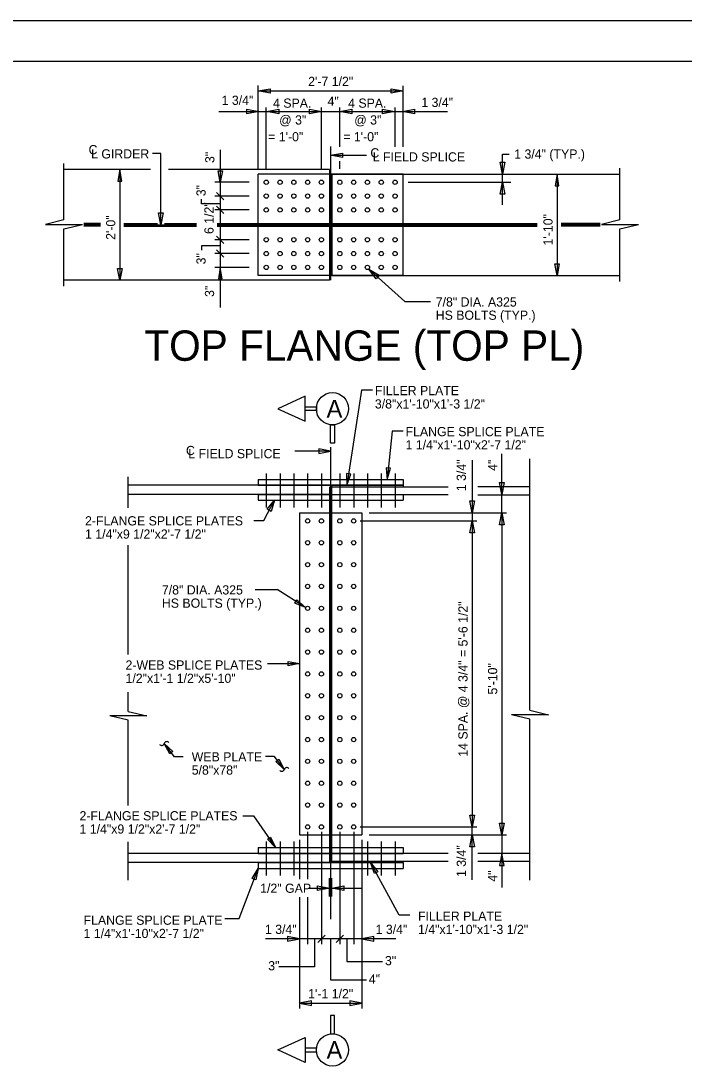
# Model space of a CAD drawing. Extents: x 1970675.2 to 1970715, y 796143 to 796167.2.
# Drawn here: x 1970692.92 to 1970701.93, y 796153.05 to 796167.25 of the extents above; entities that cross this region are included whole.
import ezdxf

# ---------------------------------------------------------------- set-up
doc = ezdxf.new("R2010")
doc.units = 0
for name, color, linetype in [('BR_AUTO DIMENSION', 7, 'Continuous'), ('BR_BORDER LINES', 7, 'Continuous'), ('BR_CENTER LINES', 7, 'Continuous'), ('BR_STRUCTURAL STEEL', 7, 'Continuous'), ('BR_TEXT', 7, 'Continuous'), ('Default', 7, 'Continuous'), ('Level 31', 7, 'Continuous')]:
    doc.layers.add(name, color=color, linetype=linetype)

msp = doc.modelspace()

# ---------------------------------------------------------------- linework, layer by layer
at = {"layer": 'BR_AUTO DIMENSION'}
for p, q in [((1970696.144, 796165.236), (1970696.144, 796166.368)), ((1970696.144, 796166.295), (1970698.113, 796166.295)), ((1970698.113, 796165.537), (1970698.113, 796166.366)), ((1970695.609, 796166.015), (1970698.716, 796166.015)), ((1970696.253, 796165.236), (1970696.253, 796166.071)), ((1970697.003, 796165.236), (1970697.003, 796166.071)), ((1970697.253, 796165.538), (1970697.253, 796166.071)), ((1970698.003, 796165.538), (1970698.003, 796166.071)), ((1970694.822, 796165.447), (1970694.706, 796165.447)), ((1970694.822, 796164.477), (1970694.822, 796165.447)), ((1970695.629, 796165.497), (1970695.629, 796163.356)), ((1970699.464, 796164.749), (1970699.464, 796165.436)), ((1970699.464, 796165.436), (1970699.551, 796165.436)), ((1970697.253, 796165.236), (1970697.253, 796165.343)), ((1970694.264, 796165.227), (1970694.264, 796163.727)), ((1970698.18, 796165.164), (1970699.574, 796165.164)), ((1970700.204, 796165.164), (1970700.204, 796163.789)), ((1970696.022, 796165.055), (1970695.553, 796165.055)), ((1970698.18, 796165.055), (1970699.574, 796165.055)), ((1970696.022, 796164.868), (1970695.553, 796164.868)), ((1970695.679, 796164.817), (1970695.579, 796164.918)), ((1970695.679, 796164.629), (1970695.579, 796164.731)), ((1970696.022, 796164.68), (1970695.553, 796164.68)), ((1970695.679, 796164.223), (1970695.579, 796164.324)), ((1970696.022, 796164.274), (1970695.553, 796164.274)), ((1970696.022, 796164.086), (1970695.553, 796164.086)), ((1970695.679, 796164.036), (1970695.579, 796164.137)), ((1970696.022, 796163.899), (1970695.553, 796163.899)), ((1970698.138, 796163.436), (1970697.647, 796163.876)), ((1970698.138, 796163.436), (1970698.486, 796163.436)), ((1970697.549, 796162.229), (1970697.349, 796160.94)), ((1970697.695, 796162.229), (1970697.549, 796162.229)), ((1970697.966, 796161.673), (1970697.896, 796161.018)), ((1970698.112, 796161.673), (1970697.966, 796161.673)), ((1970699.453, 796160.565), (1970699.453, 796161.365)), ((1970699.05, 796161.279), (1970699.05, 796160.455)), ((1970696.219, 796160.461), (1970696.365, 796160.736)), ((1970696.083, 796160.461), (1970696.219, 796160.461)), ((1970697.652, 796160.565), (1970699.516, 796160.565)), ((1970699.453, 796160.565), (1970699.453, 796156.19)), ((1970697.527, 796160.455), (1970699.113, 796160.455)), ((1970699.05, 796160.455), (1970699.05, 796156.299)), ((1970696.104, 796159.522), (1970696.4, 796159.522)), ((1970696.788, 796159.278), (1970696.4, 796159.522)), ((1970696.269, 796158.517), (1970696.707, 796158.517)), ((1970695.009, 796157.251), (1970694.868, 796157.432)), ((1970695.123, 796157.251), (1970695.009, 796157.251)), ((1970696.243, 796157.261), (1970696.358, 796157.261)), ((1970696.358, 796157.261), (1970696.499, 796157.08)), ((1970695.934, 796156.451), (1970696.08, 796156.451)), ((1970696.08, 796156.451), (1970696.381, 796156.018)), ((1970696.816, 796156.231), (1970696.816, 796155.589)), ((1970697.003, 796156.231), (1970697.003, 796154.706)), ((1970697.253, 796156.231), (1970697.253, 796154.706)), ((1970697.441, 796156.231), (1970697.441, 796154.706)), ((1970697.527, 796156.299), (1970699.113, 796156.299)), ((1970699.05, 796155.58), (1970699.05, 796156.299)), ((1970696.707, 796156.122), (1970696.707, 796155.589)), ((1970697.55, 796156.122), (1970697.55, 796153.832)), ((1970697.652, 796156.19), (1970699.516, 796156.19)), ((1970699.453, 796156.19), (1970699.453, 796155.477)), ((1970698.059, 796155.102), (1970697.671, 796155.815)), ((1970695.886, 796155.056), (1970696.144, 796155.736)), ((1970697.113, 796155.355), (1970697.113, 796155.601)), ((1970697.144, 796155.355), (1970697.144, 796155.601)), ((1970696.826, 796155.467), (1970697.113, 796155.467)), ((1970697.144, 796155.467), (1970697.56, 796155.467)), ((1970696.707, 796155.347), (1970696.707, 796153.832)), ((1970696.816, 796155.347), (1970696.816, 796154.706)), ((1970698.205, 796155.102), (1970698.059, 796155.102)), ((1970695.693, 796155.056), (1970695.886, 796155.056)), ((1970697.054, 796154.829), (1970696.953, 796154.729)), ((1970697.304, 796154.829), (1970697.203, 796154.729)), ((1970698.014, 796154.779), (1970696.243, 796154.779)), ((1970696.91, 796154.779), (1970696.91, 796154.401)), ((1970697.128, 796154.779), (1970697.128, 796154.221)), ((1970697.347, 796154.779), (1970697.347, 796154.471)), ((1970696.91, 796154.401), (1970696.423, 796154.401)), ((1970697.347, 796154.471), (1970697.834, 796154.471)), ((1970697.128, 796154.221), (1970697.615, 796154.221)), ((1970696.707, 796153.905), (1970697.55, 796153.905))]:
    msp.add_line(p, q, dxfattribs=at)
for points in [[(1970696.307, 796166.264), (1970696.144, 796166.295), (1970696.307, 796166.326)], [(1970697.95, 796166.326), (1970698.113, 796166.295), (1970697.95, 796166.264)], [(1970695.989, 796166.046), (1970696.152, 796166.015), (1970695.989, 796165.984)], [(1970696.424, 796165.984), (1970696.261, 796166.015), (1970696.424, 796166.046)], [(1970696.841, 796166.046), (1970697.003, 796166.015), (1970696.841, 796165.984)], [(1970697.416, 796165.984), (1970697.253, 796166.015), (1970697.416, 796166.046)], [(1970697.833, 796166.046), (1970697.996, 796166.015), (1970697.833, 796165.984)], [(1970698.268, 796165.984), (1970698.105, 796166.015), (1970698.268, 796166.046)], [(1970697.291, 796165.389), (1970697.128, 796165.421), (1970697.291, 796165.452)], [(1970699.495, 796165.327), (1970699.464, 796165.164), (1970699.432, 796165.327)], [(1970694.238, 796165.071), (1970694.29, 796165.071), (1970694.264, 796165.227)], [(1970695.659, 796165.211), (1970695.629, 796165.055), (1970695.599, 796165.211)], [(1970700.178, 796165.008), (1970700.23, 796165.008), (1970700.204, 796165.164)], [(1970699.432, 796164.893), (1970699.464, 796165.055), (1970699.495, 796164.893)], [(1970694.853, 796164.639), (1970694.822, 796164.477), (1970694.79, 796164.639)], [(1970694.294, 796163.883), (1970694.264, 796163.727), (1970694.234, 796163.883)], [(1970695.603, 796163.742), (1970695.655, 796163.742), (1970695.629, 796163.899)], [(1970697.747, 796163.744), (1970697.647, 796163.876), (1970697.788, 796163.791)], [(1970700.234, 796163.945), (1970700.204, 796163.789), (1970700.174, 796163.945)], [(1970696.966, 796161.371), (1970697.128, 796161.403), (1970696.966, 796161.434)], [(1970697.883, 796161.176), (1970697.896, 796161.018), (1970697.942, 796161.17)], [(1970697.343, 796161.098), (1970697.349, 796160.94), (1970697.402, 796161.089)], [(1970699.484, 796160.977), (1970699.453, 796160.815), (1970699.422, 796160.977)], [(1970696.265, 796160.613), (1970696.365, 796160.736), (1970696.318, 796160.585)], [(1970699.082, 796160.727), (1970699.05, 796160.565), (1970699.019, 796160.727)], [(1970699.422, 796160.402), (1970699.453, 796160.565), (1970699.484, 796160.402)], [(1970699.019, 796160.293), (1970699.05, 796160.455), (1970699.082, 796160.293)], [(1970696.642, 796159.339), (1970696.67, 796159.383), (1970696.788, 796159.278)], [(1970696.551, 796158.547), (1970696.707, 796158.517), (1970696.551, 796158.487)], [(1970694.984, 796157.324), (1970694.943, 796157.292), (1970694.868, 796157.432)], [(1970696.382, 796157.187), (1970696.424, 796157.219), (1970696.499, 796157.08)], [(1970699.082, 796156.461), (1970699.05, 796156.299), (1970699.019, 796156.461)], [(1970699.484, 796156.352), (1970699.453, 796156.19), (1970699.422, 796156.352)], [(1970696.27, 796156.131), (1970696.313, 796156.161), (1970696.381, 796156.018)], [(1970699.019, 796156.027), (1970699.05, 796156.19), (1970699.082, 796156.027)], [(1970699.484, 796155.777), (1970699.453, 796155.94), (1970699.422, 796155.777)], [(1970697.768, 796155.69), (1970697.723, 796155.665), (1970697.671, 796155.815)], [(1970696.112, 796155.581), (1970696.063, 796155.6), (1970696.144, 796155.736)], [(1970696.95, 796155.498), (1970697.113, 796155.467), (1970696.95, 796155.436)], [(1970697.307, 796155.436), (1970697.144, 796155.467), (1970697.307, 796155.498)], [(1970696.544, 796154.748), (1970696.707, 796154.779), (1970696.544, 796154.81)], [(1970697.713, 796154.81), (1970697.55, 796154.779), (1970697.713, 796154.748)], [(1970696.869, 796153.936), (1970696.707, 796153.905), (1970696.869, 796153.874)], [(1970697.388, 796153.874), (1970697.55, 796153.905), (1970697.388, 796153.936)]]:
    msp.add_lwpolyline(points, close=True, dxfattribs=at)
for points in [[(1970697.128, 796165.421), (1970697.614, 796165.421)], [(1970695.629, 796164.762), (1970695.376, 796164.762), (1970695.376, 796164.823)], [(1970695.629, 796164.192), (1970695.376, 796164.192), (1970695.376, 796164.131)], [(1970697.128, 796161.403), (1970696.643, 796161.403)]]:
    msp.add_lwpolyline(points, dxfattribs=at)
at = {"layer": 'BR_BORDER LINES'}
msp.add_line((1970714.286, 796166.696), (1970677.253, 796166.696), dxfattribs=at)
at = {"layer": 'BR_CENTER LINES'}
for p, q in [((1970697.128, 796165.541), (1970697.128, 796163.727)), ((1970694.001, 796164.477), (1970693.777, 796164.477)), ((1970694.317, 796164.477), (1970694.822, 796164.477)), ((1970694.822, 796164.477), (1970695.307, 796164.477)), ((1970695.587, 796164.477), (1970699.932, 796164.477)), ((1970700.79, 796164.477), (1970700.258, 796164.477)), ((1970697.128, 796161.459), (1970697.128, 796155.048))]:
    msp.add_line(p, q, dxfattribs=at)
at = {"layer": 'BR_STRUCTURAL STEEL'}
for p, q in [((1970694.682, 796165.227), (1970693.506, 796165.227)), ((1970697.113, 796165.227), (1970694.924, 796165.227)), ((1970698.113, 796165.164), (1970696.144, 796165.164)), ((1970696.144, 796163.789), (1970696.144, 796165.164)), ((1970697.113, 796165.227), (1970697.113, 796165.164)), ((1970697.113, 796165.164), (1970697.113, 796163.789)), ((1970697.144, 796165.164), (1970697.144, 796163.789)), ((1970697.144, 796165.164), (1970701.058, 796165.164)), ((1970698.113, 796163.789), (1970698.113, 796165.164)), ((1970694.001, 796164.496), (1970693.777, 796164.496)), ((1970694.001, 796164.457), (1970693.777, 796164.457)), ((1970694.317, 796164.496), (1970694.777, 796164.496)), ((1970694.317, 796164.457), (1970695.308, 796164.457)), ((1970694.872, 796164.496), (1970695.308, 796164.496)), ((1970695.588, 796164.496), (1970697.113, 796164.496)), ((1970695.588, 796164.457), (1970697.113, 796164.457)), ((1970697.144, 796164.496), (1970699.932, 796164.496)), ((1970697.144, 796164.457), (1970699.933, 796164.457)), ((1970700.79, 796164.496), (1970700.258, 796164.496)), ((1970700.79, 796164.457), (1970700.258, 796164.457)), ((1970697.113, 796163.727), (1970693.506, 796163.727)), ((1970698.113, 796163.789), (1970696.144, 796163.789)), ((1970697.113, 796163.789), (1970697.113, 796163.727)), ((1970697.144, 796163.789), (1970701.058, 796163.789)), ((1970696.253, 796161.099), (1970696.253, 796160.639)), ((1970696.441, 796161.099), (1970696.441, 796160.639)), ((1970696.628, 796161.099), (1970696.628, 796160.639)), ((1970696.816, 796161.099), (1970696.816, 796160.639)), ((1970697.003, 796161.099), (1970697.003, 796160.639)), ((1970697.253, 796161.099), (1970697.253, 796160.639)), ((1970697.441, 796161.099), (1970697.441, 796160.639)), ((1970697.628, 796161.099), (1970697.628, 796160.639)), ((1970697.816, 796161.099), (1970697.816, 796160.639)), ((1970698.003, 796161.099), (1970698.003, 796160.639)), ((1970697.113, 796160.94), (1970694.378, 796160.94)), ((1970696.144, 796161.018), (1970696.144, 796160.94)), ((1970696.144, 796161.018), (1970698.113, 796161.018)), ((1970696.144, 796160.94), (1970698.113, 796160.94)), ((1970697.113, 796160.916), (1970697.113, 796155.815)), ((1970697.144, 796155.815), (1970697.144, 796160.94)), ((1970698.113, 796160.94), (1970697.144, 796160.94)), ((1970697.144, 796160.916), (1970697.144, 796160.94)), ((1970697.144, 796160.916), (1970698.725, 796160.916)), ((1970697.144, 796160.916), (1970698.113, 796160.916)), ((1970698.113, 796161.018), (1970698.113, 796160.94)), ((1970698.113, 796160.94), (1970698.113, 796160.916)), ((1970699.836, 796160.916), (1970699.128, 796160.916)), ((1970697.113, 796160.815), (1970694.378, 796160.815)), ((1970696.144, 796160.815), (1970696.144, 796160.736)), ((1970696.144, 796160.815), (1970698.113, 796160.815)), ((1970697.144, 796160.815), (1970698.725, 796160.815)), ((1970698.113, 796160.815), (1970698.113, 796160.736)), ((1970699.836, 796160.807), (1970699.128, 796160.807)), ((1970696.144, 796160.736), (1970698.113, 796160.736)), ((1970696.707, 796160.565), (1970697.55, 796160.565)), ((1970696.707, 796160.565), (1970696.707, 796156.19)), ((1970697.55, 796160.565), (1970697.55, 796156.19)), ((1970696.253, 796156.099), (1970696.253, 796155.639)), ((1970696.441, 796156.099), (1970696.441, 796155.639)), ((1970696.628, 796156.099), (1970696.628, 796155.639)), ((1970696.707, 796156.19), (1970697.55, 796156.19)), ((1970696.816, 796156.099), (1970696.816, 796155.639)), ((1970697.003, 796156.099), (1970697.003, 796155.639)), ((1970697.253, 796156.099), (1970697.253, 796155.639)), ((1970697.441, 796156.099), (1970697.441, 796155.639)), ((1970697.628, 796156.099), (1970697.628, 796155.639)), ((1970697.816, 796156.099), (1970697.816, 796155.639)), ((1970698.003, 796156.099), (1970698.003, 796155.639)), ((1970698.725, 796155.94), (1970694.378, 796155.94)), ((1970696.144, 796156.018), (1970696.144, 796155.94)), ((1970696.144, 796156.018), (1970698.113, 796156.018)), ((1970696.144, 796155.94), (1970698.113, 796155.94)), ((1970698.113, 796156.018), (1970698.113, 796155.94)), ((1970699.836, 796155.94), (1970699.128, 796155.94)), ((1970697.113, 796155.815), (1970694.378, 796155.815)), ((1970696.144, 796155.815), (1970696.144, 796155.736)), ((1970696.144, 796155.815), (1970698.113, 796155.815)), ((1970697.144, 796155.83), (1970698.113, 796155.83)), ((1970697.144, 796155.815), (1970697.144, 796155.83)), ((1970698.725, 796155.83), (1970697.144, 796155.83)), ((1970698.113, 796155.815), (1970697.144, 796155.815)), ((1970698.113, 796155.815), (1970698.113, 796155.83)), ((1970698.113, 796155.815), (1970698.113, 796155.736)), ((1970699.836, 796155.83), (1970699.128, 796155.83)), ((1970696.144, 796155.736), (1970698.113, 796155.736))]:
    msp.add_line(p, q, dxfattribs=at)
for centre in [(1970696.253, 796165.055), (1970696.253, 796165.055), (1970696.441, 796165.055), (1970696.441, 796165.055), (1970696.628, 796165.055), (1970696.628, 796165.055), (1970696.816, 796165.055), (1970696.816, 796165.055), (1970697.003, 796165.055), (1970697.003, 796165.055), (1970697.253, 796165.055), (1970697.253, 796165.055), (1970697.441, 796165.055), (1970697.441, 796165.055), (1970697.628, 796165.055), (1970697.628, 796165.055), (1970697.816, 796165.055), (1970697.816, 796165.055), (1970698.003, 796165.055), (1970698.003, 796165.055), (1970696.253, 796164.868), (1970696.253, 796164.868), (1970696.441, 796164.868), (1970696.441, 796164.868), (1970696.628, 796164.868), (1970696.628, 796164.868), (1970696.816, 796164.868), (1970696.816, 796164.868), (1970697.003, 796164.868), (1970697.003, 796164.868), (1970697.253, 796164.868), (1970697.253, 796164.868), (1970697.441, 796164.868), (1970697.441, 796164.868), (1970697.628, 796164.868), (1970697.628, 796164.868), (1970697.816, 796164.868), (1970697.816, 796164.868), (1970698.003, 796164.868), (1970698.003, 796164.868), (1970696.253, 796164.68), (1970696.253, 796164.68), (1970696.441, 796164.68), (1970696.441, 796164.68), (1970696.628, 796164.68), (1970696.628, 796164.68), (1970696.816, 796164.68), (1970696.816, 796164.68), (1970697.003, 796164.68), (1970697.003, 796164.68), (1970697.253, 796164.68), (1970697.253, 796164.68), (1970697.441, 796164.68), (1970697.441, 796164.68), (1970697.628, 796164.68), (1970697.628, 796164.68), (1970697.816, 796164.68), (1970697.816, 796164.68), (1970698.003, 796164.68), (1970698.003, 796164.68), (1970696.253, 796164.274), (1970696.253, 796164.274), (1970696.441, 796164.274), (1970696.441, 796164.274), (1970696.628, 796164.274), (1970696.628, 796164.274), (1970696.816, 796164.274), (1970696.816, 796164.274), (1970697.003, 796164.274), (1970697.003, 796164.274), (1970697.253, 796164.274), (1970697.253, 796164.274), (1970697.441, 796164.274), (1970697.441, 796164.274), (1970697.628, 796164.274), (1970697.628, 796164.274), (1970697.816, 796164.274), (1970697.816, 796164.274), (1970698.003, 796164.274), (1970698.003, 796164.274), (1970696.253, 796164.086), (1970696.253, 796164.086), (1970696.441, 796164.086), (1970696.441, 796164.086), (1970696.628, 796164.086), (1970696.628, 796164.086), (1970696.816, 796164.086), (1970696.816, 796164.086), (1970697.003, 796164.086), (1970697.003, 796164.086), (1970697.253, 796164.086), (1970697.253, 796164.086), (1970697.441, 796164.086), (1970697.441, 796164.086), (1970697.628, 796164.086), (1970697.628, 796164.086), (1970697.816, 796164.086), (1970697.816, 796164.086), (1970698.003, 796164.086), (1970698.003, 796164.086), (1970696.253, 796163.899), (1970696.253, 796163.899), (1970696.441, 796163.899), (1970696.441, 796163.899), (1970696.628, 796163.899), (1970696.628, 796163.899), (1970696.816, 796163.899), (1970696.816, 796163.899), (1970697.003, 796163.899), (1970697.003, 796163.899), (1970697.253, 796163.899), (1970697.253, 796163.899), (1970697.441, 796163.899), (1970697.441, 796163.899), (1970697.628, 796163.899), (1970697.628, 796163.899), (1970697.816, 796163.899), (1970697.816, 796163.899), (1970698.003, 796163.899), (1970698.003, 796163.899), (1970696.816, 796160.455), (1970697.003, 796160.455), (1970697.253, 796160.455), (1970697.441, 796160.455), (1970696.816, 796160.158), (1970697.003, 796160.158), (1970697.253, 796160.158), (1970697.441, 796160.158), (1970696.816, 796159.861), (1970697.003, 796159.861), (1970697.253, 796159.861), (1970697.441, 796159.861), (1970696.816, 796159.565), (1970697.003, 796159.565), (1970697.253, 796159.565), (1970697.441, 796159.565), (1970696.816, 796159.268), (1970697.003, 796159.268), (1970697.253, 796159.268), (1970697.441, 796159.268), (1970696.816, 796158.971), (1970697.003, 796158.971), (1970697.253, 796158.971), (1970697.441, 796158.971), (1970696.816, 796158.674), (1970697.003, 796158.674), (1970697.253, 796158.674), (1970697.441, 796158.674), (1970696.816, 796158.377), (1970697.003, 796158.377), (1970697.253, 796158.377), (1970697.441, 796158.377), (1970696.816, 796158.08), (1970697.003, 796158.08), (1970697.253, 796158.08), (1970697.441, 796158.08), (1970696.816, 796157.783), (1970697.003, 796157.783), (1970697.253, 796157.783), (1970697.441, 796157.783), (1970696.816, 796157.486), (1970697.003, 796157.486), (1970697.253, 796157.486), (1970697.441, 796157.486), (1970696.816, 796157.19), (1970697.003, 796157.19), (1970697.253, 796157.19), (1970697.441, 796157.19), (1970696.816, 796156.893), (1970697.003, 796156.893), (1970697.253, 796156.893), (1970697.441, 796156.893), (1970696.816, 796156.596), (1970697.003, 796156.596), (1970697.253, 796156.596), (1970697.441, 796156.596), (1970696.816, 796156.299), (1970697.003, 796156.299), (1970697.253, 796156.299), (1970697.441, 796156.299)]:
    msp.add_circle(centre, 0.0293, dxfattribs=at)
at = {"layer": 'BR_TEXT'}
for points in [[(1970696.784, 796162.148), (1970696.409, 796161.979), (1970696.784, 796161.81)], [(1970696.935, 796161.954), (1970696.784, 796161.954), (1970696.784, 796162.004), (1970696.935, 796162.004)], [(1970697.179, 796161.51), (1970697.128, 796161.51), (1970697.128, 796161.76), (1970697.179, 796161.76)], [(1970697.179, 796153.739), (1970697.128, 796153.739), (1970697.128, 796153.489), (1970697.179, 796153.489)], [(1970696.784, 796153.101), (1970696.409, 796153.27), (1970696.784, 796153.439)], [(1970696.935, 796153.295), (1970696.784, 796153.295), (1970696.784, 796153.245), (1970696.935, 796153.245)]]:
    msp.add_lwpolyline(points, close=True, dxfattribs=at)
for centre in [(1970697.153, 796161.979), (1970697.153, 796153.27)]:
    msp.add_circle(centre, 0.219, dxfattribs=at)
at = {"layer": 'Default'}
for p, q in [((1970693.506, 796164.543), (1970693.506, 796165.31)), ((1970701.058, 796164.543), (1970701.058, 796165.248)), ((1970693.506, 796164.543), (1970693.254, 796164.482)), ((1970693.254, 796164.482), (1970693.758, 796164.482)), ((1970693.506, 796164.422), (1970693.758, 796164.482)), ((1970701.058, 796164.543), (1970700.806, 796164.482)), ((1970700.806, 796164.482), (1970701.31, 796164.482)), ((1970701.058, 796164.422), (1970701.31, 796164.482)), ((1970693.506, 796163.644), (1970693.506, 796164.422)), ((1970701.058, 796163.706), (1970701.058, 796164.422)), ((1970699.836, 796157.884), (1970699.836, 796161.297)), ((1970694.378, 796160.633), (1970694.378, 796161.054)), ((1970694.378, 796158.643), (1970694.378, 796160.127)), ((1970694.378, 796157.868), (1970694.378, 796158.13)), ((1970694.63, 796157.807), (1970694.127, 796157.807)), ((1970694.378, 796157.747), (1970694.127, 796157.807)), ((1970694.378, 796157.868), (1970694.63, 796157.807)), ((1970700.088, 796157.823), (1970699.585, 796157.823)), ((1970699.836, 796157.763), (1970699.585, 796157.823)), ((1970699.836, 796157.884), (1970700.088, 796157.823)), ((1970694.378, 796156.589), (1970694.378, 796157.747)), ((1970699.836, 796155.575), (1970699.836, 796157.763)), ((1970694.378, 796155.575), (1970694.378, 796156.098))]:
    msp.add_line(p, q, dxfattribs=at)
for centre, start, end in [((1970694.833, 796157.443), 219.9477, 342.4119), ((1970694.903, 796157.421), 39.9477, 162.4119), ((1970696.464, 796157.091), 219.9477, 342.4119), ((1970696.534, 796157.069), 39.9477, 162.4119)]:
    msp.add_arc(centre, 0.0366, start, end, dxfattribs=at)
at = {"layer": 'Level 31'}
msp.add_line((1970714.836, 796167.246), (1970675.236, 796167.246), dxfattribs=at)

# ---------------------------------------------------------------- texts
at = {"layer": 'BR_AUTO DIMENSION'}
for s, p in [('1 3/4"', (1970698.965, 796160.859)), ('4"', (1970699.391, 796161.135)), ('14 SPA. @ 4 3/4" = 5\'-6 1/2"', (1970698.988, 796157.253)), ('5\'-10"', (1970699.391, 796158.097)), ('1 3/4"', (1970698.965, 796155.619)), ('4"', (1970699.391, 796155.555))]:
    msp.add_text(s, height=0.125, rotation=90, dxfattribs=at).set_placement(p)
at = {"layer": 'BR_TEXT'}
for s, height, p in [('2\'-7 1/2"', 0.125, (1970696.823, 796166.362)), ('1 3/4"', 0.125, (1970695.647, 796166.106)), ('4 SPA. ', 0.125, (1970696.346, 796166.067)), ('4"', 0.125, (1970697.086, 796166.093)), ('4 SPA. ', 0.125, (1970697.366, 796166.067)), ('1 3/4"', 0.125, (1970698.36, 796166.077)), ('@ 3" ', 0.125, (1970696.429, 796165.839)), ('@ 3" ', 0.125, (1970697.449, 796165.839)), ('= 1\'-0"', 0.125, (1970696.28, 796165.611)), ('= 1\'-0"', 0.125, (1970697.3, 796165.611)), ('C', 0.125, (1970693.84, 796165.435)), ('L GIRDER', 0.125, (1970693.874, 796165.378)), ('C', 0.125, (1970697.668, 796165.392)), ('L FIELD SPLICE', 0.125, (1970697.7, 796165.337)), ('1 3/4" (TYP.)', 0.125, (1970699.622, 796165.376)), ('7/8" DIA. A325', 0.125, (1970698.556, 796163.367)), ('HS BOLTS (TYP.)', 0.125, (1970698.556, 796163.187)), ('TOP FLANGE (TOP PL)', 0.4125, (1970694.597, 796162.63)), ('FILLER PLATE', 0.125, (1970697.729, 796162.163)), ('A', 0.24, (1970697.073, 796161.859)), ('3/8"x1\'-10"x1\'-3 1/2"', 0.125, (1970697.729, 796161.982)), ('FLANGE SPLICE PLATE', 0.125, (1970698.146, 796161.606)), ('C', 0.125, (1970695.163, 796161.349)), ('1 1/4"x1\'-10"x2\'-7 1/2"', 0.125, (1970698.146, 796161.426)), ('L FIELD SPLICE', 0.125, (1970695.195, 796161.307)), ('2-FLANGE SPLICE PLATES', 0.125, (1970693.792, 796160.394)), ('1 1/4"x9 1/2"x2\'-7 1/2"', 0.125, (1970693.792, 796160.214)), ('7/8" DIA. A325', 0.125, (1970694.836, 796159.456)), ('HS BOLTS (TYP.)', 0.125, (1970694.836, 796159.276)), ('2-WEB SPLICE PLATES', 0.125, (1970694.342, 796158.436)), ('1/2"x1\'-1 1/2"x5\'-10"', 0.125, (1970694.342, 796158.256)), ('WEB PLATE', 0.125, (1970695.241, 796157.189)), ('5/8"x78"', 0.125, (1970695.241, 796157.009)), ('2-FLANGE SPLICE PLATES', 0.125, (1970693.717, 796156.388)), ('1 1/4"x9 1/2"x2\'-7 1/2"', 0.125, (1970693.717, 796156.208)), ('1/2" GAP', 0.125, (1970696.171, 796155.404)), ('FLANGE SPLICE PLATE', 0.125, (1970693.772, 796154.97)), ('FILLER PLATE', 0.125, (1970698.315, 796155.025)), ('1 3/4"', 0.125, (1970696.236, 796154.846)), ('1 3/4"', 0.125, (1970697.739, 796154.846)), ('1/4"x1\'-10"x1\'-3 1/2"', 0.125, (1970698.315, 796154.845)), ('1 1/4"x1\'-10"x2\'-7 1/2"', 0.125, (1970693.772, 796154.79)), ('3"', 0.125, (1970697.866, 796154.421)), ('3"', 0.125, (1970696.28, 796154.351)), ('4"', 0.125, (1970697.647, 796154.171)), ('1\'-1 1/2"', 0.125, (1970696.823, 796153.972)), ('A', 0.24, (1970697.073, 796153.15))]:
    msp.add_text(s, height=height, dxfattribs=at).set_placement(p)
for s, p in [('3"', (1970695.549, 796165.316)), ('3"', (1970695.43, 796164.865)), ('6 1/2"', (1970695.538, 796164.352)), ('2\'-0"', (1970694.203, 796164.273)), ('1\'-10"', (1970700.143, 796164.197)), ('3"', (1970695.43, 796163.939)), ('3"', (1970695.545, 796163.498))]:
    msp.add_text(s, height=0.125, rotation=90, dxfattribs=at).set_placement(p)

doc.saveas('drawing.dxf')
